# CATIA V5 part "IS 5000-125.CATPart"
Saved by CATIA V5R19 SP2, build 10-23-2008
Part number: IS 5000-125
Bounding box of the stored display mesh (mm): x -59.975 to 59.975, y -59.975 to 59.975, z 0 to 390
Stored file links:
  C:\Users\Bora\Desktop\3D Katı model\IS serisi\IS 5000\IS 5000-125.CATPart
  C:\Program Files\Dassault Systemes\B19\intel_a\reffiles\standard\MetricThickPitch.txt
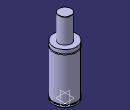
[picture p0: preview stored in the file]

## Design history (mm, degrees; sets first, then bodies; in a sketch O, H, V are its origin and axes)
Body1 (main body)
  Sketch1 on yz-plane, origin (0, 0, 0), H (0, 1, 0), V (0, 0, 1)
    point P1 (60, 242)
    point P4 (60, 237)
    point P7 (32.5, 389)
    point P9 (32.5, 389)
    point P13 (60, 242)
    point P14 (60, 237)
    line L1 (60, 242) -> (60, 262)
    line L2 (60, 13) -> (60, 237)
    line L3 (56, 13) -> (56, 8)
    arc A1 centre (31.5, 389) radius 1 from (32.5, 389) to (31.5, 390) ccw
    line L4 (32.5, 389) -> (32.5, 262)
    line L5 (60, 0) -> (60, 8)
    arc A2 centre (60, 239.5) radius 2.5 from (60, 242) to (60, 237) ccw
    line L6 (31.5, 390) -> (0, 390)
    point P15 (0, 390)
    line L7 (32.5, 262) -> (60, 262)
    line L8 (0, 0) -> (60, 0)
    line L9 (56, 13) -> (60, 13)
    line L10 (56, 8) -> (60, 8)
    coincidence: P15 V, P1 P13, P4 P14, P7 P9
    tangency: L6 A1
    horizontal: L7 H, L8 H, L9 H, L10 H
  Shaft1: profile Sketch1, axis Sketch1.V, angle 360
  Sketch2 on face of Shaft1 from Sketch1.L8, origin (0, 0, 0), H (1, 0, 0), V (0, -1, 0)
    point P1 (40, 0)
    distance P1 V = 40
  Hole1: placed by Sketch2, at (40, 0, 0) direction (0, 0, 1), diameter 8.376, depth 16, threaded "M10", thread diameter 10, thread depth 16, pitch 1.5
  CircPattern1: of Hole1, instances 4, angular step 90, axis from xy-plane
